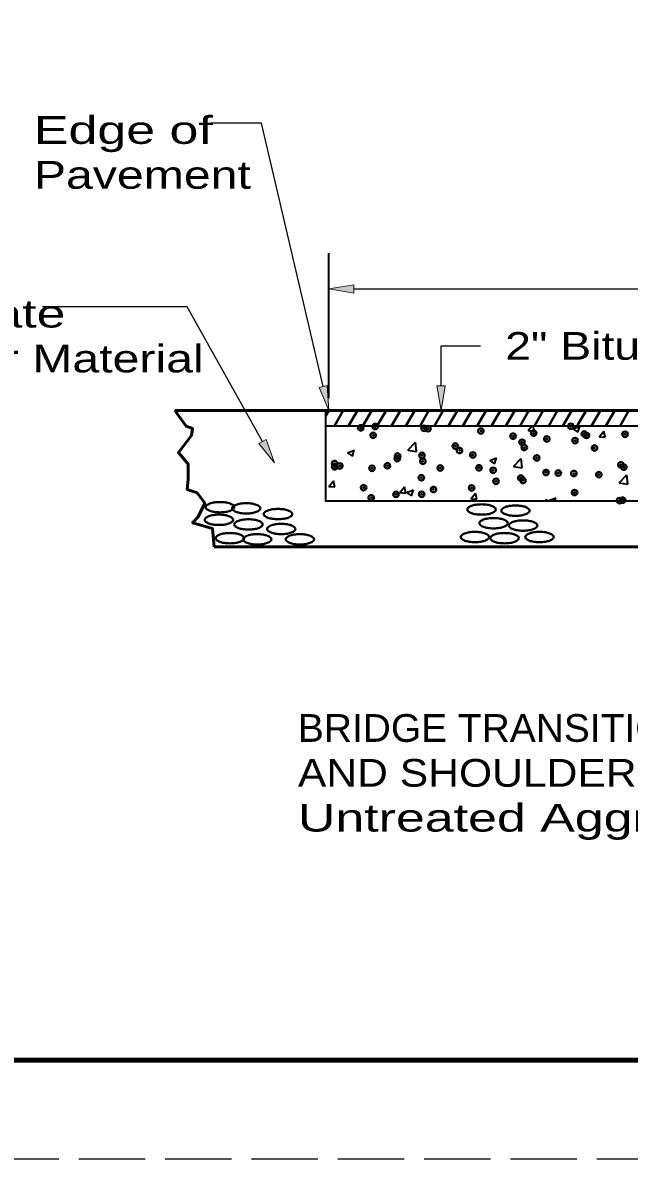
# Model space of a CAD drawing. Extents: x 36.4 to 71.7, y 0.5 to 22.5.
# Drawn here: x 50.93 to 53.99, y 0.48 to 6.22 of the extents above; entities that cross this region are included whole.
import ezdxf

# ---------------------------------------------------------------- set-up
doc = ezdxf.new("R2010")
doc.units = 0
doc.header["$LTSCALE"] = 0.056
doc.header["$PDMODE"] = 32
doc.header["$PDSIZE"] = 0.028
doc.linetypes.add('LONG_DASHED', pattern=[7.5, 6, -1.5])
for name, color, linetype, lineweight in [('1', 7, 'Continuous', 40), ('3', 7, 'Continuous', 13), ('6', 7, 'Continuous', 13)]:
    doc.layers.add(name, color=color, linetype=linetype, lineweight=lineweight)

msp = doc.modelspace()

# ---------------------------------------------------------------- hatches: boundary and pattern name
at = {"layer": '1'}
msp.add_hatch(color=256, dxfattribs=at).paths.add_polyline_path([(52.59792, 4.85283), (52.59792, 4.8945), (52.47292, 4.87358), (52.47292, 4.87358)])
at = {"layer": '3'}
for points in [[(52.46458, 4.38558), (52.42408, 4.376), (52.47292, 4.25908), (52.47292, 4.25908)], [(53.05992, 4.38408), (53.01825, 4.38408), (53.03908, 4.25908), (53.03908, 4.25908)], [(52.15567, 4.11383), (52.11933, 4.09342), (52.19867, 3.99458), (52.19867, 3.99458)]]:
    msp.add_hatch(color=256, dxfattribs=at).paths.add_polyline_path(points)

# ---------------------------------------------------------------- linework, layer by layer
at = {"layer": '1', "lineweight": 35}
for p, q in [((52.47292, 4.3215), (52.47292, 5.05367)), ((53.47892, 4.1585), (53.49825, 4.1815)), ((53.47892, 4.1585), (53.50883, 4.15592)), ((53.50883, 4.15592), (53.50408, 4.1815)), ((53.70483, 4.16767), (53.73983, 4.18108)), ((53.70483, 4.16767), (53.72975, 4.15092)), ((53.72975, 4.15092), (53.73983, 4.18108)), ((53.83758, 4.12717), (53.86167, 4.15592)), ((53.86742, 4.1245), (53.86167, 4.15583)), ((52.87092, 4.05933), (52.90983, 4.09992)), ((52.91542, 4.05242), (52.90992, 4.09992)), ((53.83758, 4.12717), (53.86742, 4.1245)), ((52.56617, 4.04642), (52.60117, 4.05992)), ((52.56617, 4.04642), (52.59108, 4.02967)), ((52.59108, 4.02967), (52.60117, 4.05992)), ((52.87092, 4.05933), (52.91542, 4.0525)), ((53.28475, 4.00642), (53.31975, 4.01983)), ((53.30958, 3.98958), (53.31975, 4.01983)), ((53.28475, 4.00642), (53.30958, 3.98967)), ((53.40458, 3.97658), (53.4435, 4.01717)), ((53.40458, 3.97658), (53.449, 3.96967)), ((53.449, 3.96967), (53.4435, 4.01717)), ((52.47242, 3.87658), (52.4965, 3.90525)), ((52.50233, 3.87392), (52.4965, 3.90525)), ((53.93817, 3.89383), (53.97708, 3.93442)), ((53.98267, 3.88692), (53.97708, 3.93442)), ((52.47242, 3.87658), (52.50233, 3.87392)), ((52.83108, 3.84517), (52.85517, 3.87392)), ((52.86092, 3.84258), (52.85517, 3.87392)), ((52.86467, 3.84517), (52.89967, 3.85858)), ((52.8895, 3.82833), (52.89967, 3.85858)), ((52.8895, 3.82833), (52.89967, 3.85858)), ((53.93817, 3.89383), (53.98267, 3.88692)), ((52.83108, 3.84517), (52.86092, 3.84258)), ((52.86467, 3.84517), (52.8895, 3.82833)), ((53.18967, 3.81383), (53.21375, 3.8425)), ((53.18967, 3.81383), (53.21958, 3.81117)), ((53.21958, 3.81117), (53.21375, 3.8425)), ((53.56575, 3.80325), (53.57242, 3.81117)), ((53.57392, 3.80325), (53.57242, 3.81117)), ((53.58317, 3.80508), (53.61817, 3.8185)), ((53.58317, 3.80508), (53.58592, 3.80325)), ((53.61308, 3.80325), (53.61817, 3.8185))]:
    msp.add_line(p, q, dxfattribs=at)
at = {"layer": '1', "lineweight": 25}
msp.add_line((52.59792, 4.87367), (58.88025, 4.87367), dxfattribs=at)
at = {"layer": '1', "lineweight": 53}
msp.add_line((51.69492, 4.25908), (55.71225, 4.25908), dxfattribs=at)
at = {"layer": '1'}
for p, q in [((52.45633, 4.2305), (52.47292, 4.25908)), ((52.50025, 4.1815), (52.54508, 4.25908)), ((52.57242, 4.1815), (52.61725, 4.25908)), ((52.64458, 4.1815), (52.68942, 4.25908)), ((52.71675, 4.1815), (52.76158, 4.25908)), ((52.78892, 4.1815), (52.83375, 4.25908)), ((52.86108, 4.1815), (52.90592, 4.25908)), ((52.93325, 4.1815), (52.97808, 4.25908)), ((53.00542, 4.1815), (53.05025, 4.25908)), ((53.07758, 4.1815), (53.12242, 4.25908)), ((53.14975, 4.1815), (53.19458, 4.25908)), ((53.22192, 4.1815), (53.26675, 4.25908)), ((53.29417, 4.1815), (53.33892, 4.25908)), ((53.36633, 4.1815), (53.41108, 4.25908)), ((53.4385, 4.1815), (53.48325, 4.25908)), ((53.51067, 4.1815), (53.55542, 4.25908)), ((53.58283, 4.1815), (53.62758, 4.25908)), ((53.655, 4.1815), (53.69975, 4.25908)), ((53.72717, 4.1815), (53.77192, 4.25908)), ((53.79933, 4.1815), (53.84408, 4.25908)), ((53.8715, 4.1815), (53.91625, 4.25908)), ((53.94367, 4.1815), (53.98842, 4.25908))]:
    msp.add_line(p, q, dxfattribs=at)
at = {"layer": '1', "linetype": 'LONG_DASHED', "lineweight": 25}
msp.add_line((71.60142, 0.47742), (36.40142, 0.47742), dxfattribs=at)
at = {"layer": '1', "lineweight": 158}
msp.add_lwpolyline([(71.51808, 21.97742), (71.51808, 0.97742), (39.01808, 0.97742)], dxfattribs=at)
at = {"layer": '1', "lineweight": 13}
msp.add_lwpolyline([(52.59792, 4.85283), (52.59792, 4.8945), (52.47292, 4.87358), (52.47292, 4.87358)], close=True, dxfattribs=at)
at = {"layer": '1', "lineweight": 53}
for points in [[(51.69492, 4.25908), (51.75142, 4.18008), (51.78458, 4.1685), (51.77908, 4.13367), (51.71275, 4.04675), (51.7625, 3.98875), (51.7625, 3.91342), (51.75692, 3.86125), (51.80667, 3.84383), (51.84533, 3.79167), (51.81225, 3.72208), (51.78458, 3.69308), (51.88408, 3.66408), (51.89333, 3.57133)], [(55.71417, 3.809), (55.71417, 3.57133), (51.89333, 3.57133)]]:
    msp.add_lwpolyline(points, dxfattribs=at)
at = {"layer": '1', "lineweight": 35}
for points in [[(52.45633, 4.25908), (52.45633, 4.1815), (55.71225, 4.1815)], [(52.45633, 4.1815), (52.45633, 3.80325), (55.71417, 3.80325)]]:
    msp.add_lwpolyline(points, dxfattribs=at)
at = {"layer": '1'}
for centre, radius, start, end in [((51.8905, 3.73858), 0.05453, 109.95668, 131.23889), ((51.90975, 3.68525), 0.11118, 98.4919, 109.89511), ((51.9225, 3.59967), 0.19777, 89.93573, 98.48922), ((51.92292, 3.60025), 0.19721, 81.49885, 90.05234), ((51.93567, 3.68483), 0.11159, 70.15769, 81.5609), ((51.95492, 3.73883), 0.05433, 48.63999, 69.9222), ((52.04242, 3.67942), 0.11118, 98.4919, 109.89511), ((52.05575, 3.59383), 0.19781, 90.09713, 98.65062), ((52.055, 3.59442), 0.19725, 81.33699, 89.89049), ((52.06833, 3.67942), 0.11118, 70.10489, 81.5081), ((51.86183, 3.77142), 0.01094, 131.65707, 180.41795), ((51.86175, 3.77133), 0.01084, 179.79866, 228.55954), ((51.8905, 3.80417), 0.05453, 228.76111, 250.04332), ((51.90975, 3.8575), 0.11118, 250.10489, 261.5081), ((51.917, 3.53592), 0.19777, 89.93573, 98.48922), ((51.92308, 3.94308), 0.19781, 261.34937, 269.90286), ((51.91742, 3.5365), 0.19721, 81.49885, 90.05234), ((51.92233, 3.9425), 0.19725, 270.10951, 278.663), ((51.93567, 3.85792), 0.11159, 278.43909, 289.84231), ((51.95492, 3.80392), 0.05433, 290.0778, 311.36001), ((51.9945, 3.76558), 0.01098, 180.06351, 228.82439), ((51.99442, 3.7655), 0.01089, 130.95574, 179.71662), ((52.02317, 3.73275), 0.05453, 109.95668, 131.23889), ((52.02317, 3.79833), 0.05453, 228.76111, 250.04332), ((51.98367, 3.77142), 0.01089, 310.95574, 359.71662), ((51.98358, 3.77133), 0.01098, 0.06351, 48.82439), ((52.04242, 3.85167), 0.11118, 250.10489, 261.5081), ((52.05517, 3.93725), 0.19777, 261.51077, 270.06427), ((52.05558, 3.93667), 0.19721, 269.94766, 278.50115), ((52.06833, 3.85167), 0.11118, 278.4919, 289.89511), ((52.08758, 3.73275), 0.05453, 48.76111, 70.04332), ((52.08758, 3.79833), 0.05453, 289.95668, 311.23889), ((52.11633, 3.7655), 0.01089, 0.28337, 49.04425), ((52.11625, 3.76558), 0.01098, 311.1756, 359.93648), ((52.15475, 3.7365), 0.01094, 179.58205, 228.34293), ((52.15467, 3.73658), 0.01084, 131.44045, 180.20133), ((52.18342, 3.70375), 0.05453, 109.95668, 131.23889), ((52.20308, 3.6505), 0.11128, 98.70124, 110.10445), ((52.21542, 3.56492), 0.19777, 89.93573, 98.48922), ((52.21583, 3.5655), 0.19721, 81.49885, 90.05234), ((52.22817, 3.65008), 0.11169, 69.94906, 81.35227), ((52.24783, 3.704), 0.05433, 48.63999, 69.9222), ((52.27658, 3.7365), 0.01089, 0.28337, 49.04425), ((52.2765, 3.73658), 0.01098, 311.1756, 359.93648), ((53.18275, 3.75975), 0.01098, 131.1756, 179.93648), ((53.18267, 3.75983), 0.01089, 180.28337, 229.04425), ((53.21142, 3.727), 0.05453, 109.95668, 131.23889), ((53.21142, 3.79258), 0.05453, 228.76111, 250.04332), ((53.23108, 3.84583), 0.11128, 249.89554, 261.29876), ((53.23067, 3.67367), 0.11118, 98.4919, 109.89511), ((53.24342, 3.58808), 0.19777, 89.93573, 98.48922), ((53.24342, 3.93142), 0.19777, 261.51077, 270.06427), ((53.24383, 3.58867), 0.19721, 81.49885, 90.05234), ((53.24383, 3.93083), 0.19721, 269.94766, 278.50115), ((53.25658, 3.67367), 0.11118, 70.10489, 81.5081), ((53.25617, 3.84583), 0.11128, 278.70124, 290.10445), ((53.27583, 3.727), 0.05453, 48.76111, 70.04332), ((53.27583, 3.79258), 0.05453, 289.95668, 311.23889), ((53.30458, 3.75983), 0.01089, 310.95574, 359.71662), ((53.3045, 3.75975), 0.01098, 0.06351, 48.82439), ((53.35408, 3.754), 0.01098, 180.06351, 228.82439), ((53.354, 3.75392), 0.01089, 130.95574, 179.71662), ((53.38275, 3.72117), 0.05453, 109.95668, 131.23889), ((53.38275, 3.78675), 0.05453, 228.76111, 250.04332), ((53.402, 3.66783), 0.11118, 98.4919, 109.89511), ((53.402, 3.84008), 0.11118, 250.10489, 261.5081), ((53.41533, 3.58283), 0.19725, 90.10951, 98.663), ((53.41458, 3.58225), 0.19781, 81.34937, 89.90286), ((53.42792, 3.66783), 0.11118, 70.10489, 81.5081), ((53.42792, 3.84008), 0.11118, 278.4919, 289.89511), ((53.44717, 3.72117), 0.05453, 48.76111, 70.04332), ((53.44717, 3.78675), 0.05453, 289.95668, 311.23889), ((53.47592, 3.75392), 0.01089, 0.28337, 49.04425), ((53.47583, 3.754), 0.01098, 311.1756, 359.93648), ((51.85625, 3.7075), 0.01089, 130.95574, 179.71662), ((51.85625, 3.70767), 0.01089, 180.28337, 229.04425), ((51.885, 3.67475), 0.05453, 109.95668, 131.23889), ((51.885, 3.74042), 0.05453, 228.76111, 250.04332), ((51.90467, 3.6215), 0.11128, 98.70124, 110.10445), ((51.90467, 3.79367), 0.11128, 249.89554, 261.29876), ((51.917, 3.87925), 0.19777, 261.51077, 270.06427), ((51.91742, 3.87867), 0.19721, 269.94766, 278.50115), ((51.92975, 3.6215), 0.11128, 69.89554, 81.29876), ((51.92975, 3.79367), 0.11128, 278.70124, 290.10445), ((51.94942, 3.67475), 0.05453, 48.76111, 70.04332), ((51.94942, 3.74042), 0.05453, 289.95668, 311.23889), ((51.97817, 3.7075), 0.01089, 0.28337, 49.04425), ((51.97817, 3.70767), 0.01089, 310.95574, 359.71662), ((52.00558, 3.68442), 0.01098, 180.06351, 228.82439), ((52.0055, 3.68433), 0.01089, 130.95574, 179.71662), ((52.03425, 3.65158), 0.05453, 109.95668, 131.23889), ((52.03425, 3.71717), 0.05453, 228.76111, 250.04332), ((52.0535, 3.59825), 0.11118, 98.4919, 109.89511), ((52.06683, 3.51325), 0.19725, 90.10951, 98.663), ((52.06608, 3.51267), 0.19781, 81.34937, 89.90286), ((52.07942, 3.59825), 0.11118, 70.10489, 81.5081), ((52.09867, 3.65158), 0.05453, 48.76111, 70.04332), ((52.09867, 3.71717), 0.05453, 289.95668, 311.23889), ((52.12742, 3.68442), 0.01084, 359.79866, 48.55954), ((52.12733, 3.68433), 0.01094, 311.65707, 0.41795), ((52.18342, 3.76933), 0.05453, 228.76111, 250.04332), ((52.2, 3.62842), 0.05453, 109.95668, 131.23889), ((52.20267, 3.82267), 0.11118, 250.10489, 261.5081), ((52.21925, 3.57508), 0.11118, 98.4919, 109.89511), ((52.21542, 3.90825), 0.19777, 261.51077, 270.06427), ((52.23258, 3.4895), 0.19781, 90.09713, 98.65062), ((52.21583, 3.90767), 0.19721, 269.94766, 278.50115), ((52.23183, 3.49008), 0.19725, 81.33699, 89.89049), ((52.22858, 3.82308), 0.11159, 278.43909, 289.84231), ((52.24517, 3.57467), 0.11159, 70.15769, 81.5609), ((52.24783, 3.76908), 0.05433, 290.0778, 311.36001), ((52.26442, 3.62867), 0.05433, 48.63999, 69.9222), ((53.2435, 3.69025), 0.01094, 131.65707, 180.41795), ((53.24342, 3.69017), 0.01084, 179.79866, 228.55954), ((53.27217, 3.65742), 0.05453, 109.95668, 131.23889), ((53.27217, 3.723), 0.05453, 228.76111, 250.04332), ((53.2915, 3.60367), 0.11159, 98.43909, 109.84231), ((53.30425, 3.51908), 0.19721, 89.94766, 98.50115), ((53.30467, 3.5185), 0.19777, 81.51077, 90.06427), ((53.31742, 3.60408), 0.11118, 70.10489, 81.5081), ((53.33667, 3.65742), 0.05453, 48.76111, 70.04332), ((53.33667, 3.723), 0.05453, 289.95668, 311.23889), ((53.36533, 3.69025), 0.01094, 359.58205, 48.34293), ((53.36542, 3.69017), 0.01084, 311.44045, 0.20133), ((53.39275, 3.67867), 0.01094, 131.65707, 180.41795), ((53.39267, 3.67858), 0.01084, 179.79866, 228.55954), ((53.42142, 3.64583), 0.05453, 109.95668, 131.23889), ((53.41475, 3.92508), 0.19721, 261.49885, 270.05234), ((53.44067, 3.5925), 0.11118, 98.4919, 109.89511), ((53.41517, 3.92567), 0.19777, 269.93573, 278.48922), ((53.45342, 3.50692), 0.19777, 89.93573, 98.48922), ((53.45383, 3.5075), 0.19721, 81.49885, 90.05234), ((53.46658, 3.5925), 0.11118, 70.10489, 81.5081), ((53.48583, 3.64583), 0.05453, 48.76111, 70.04332), ((53.51458, 3.67867), 0.01089, 310.95574, 359.71662), ((53.5145, 3.67858), 0.01098, 0.06351, 48.82439), ((51.9115, 3.61483), 0.01084, 131.44045, 180.20133), ((51.94025, 3.582), 0.05453, 109.95668, 131.23889), ((51.95992, 3.52875), 0.11128, 98.70124, 110.10445), ((51.97225, 3.44317), 0.19777, 89.93573, 98.48922), ((51.97267, 3.44375), 0.19721, 81.49885, 90.05234), ((51.985, 3.52875), 0.11128, 69.89554, 81.29876), ((52.0535, 3.7705), 0.11118, 250.10489, 261.5081), ((52.00467, 3.582), 0.05453, 48.76111, 70.04332), ((52.06625, 3.8555), 0.19721, 261.49885, 270.05234), ((52.04975, 3.60908), 0.01094, 131.65707, 180.41795), ((52.03342, 3.61475), 0.01089, 0.28337, 49.04425), ((52.07842, 3.57625), 0.05453, 109.95668, 131.23889), ((52.09767, 3.52292), 0.11118, 98.4919, 109.89511), ((52.06667, 3.85608), 0.19777, 269.93573, 278.48922), ((52.11042, 3.43733), 0.19777, 89.93573, 98.48922), ((52.07942, 3.7705), 0.11118, 278.4919, 289.89511), ((52.11083, 3.43792), 0.19721, 81.49885, 90.05234), ((52.12358, 3.52292), 0.11118, 70.10489, 81.5081), ((52.17133, 3.66125), 0.01094, 131.65707, 180.41795), ((52.17125, 3.66117), 0.01084, 179.79866, 228.55954), ((52.14283, 3.57625), 0.05453, 48.76111, 70.04332), ((52.2, 3.694), 0.05453, 228.76111, 250.04332), ((52.1715, 3.609), 0.01098, 0.06351, 48.82439), ((52.21925, 3.74733), 0.11118, 250.10489, 261.5081), ((52.23258, 3.83292), 0.19781, 261.34937, 269.90286), ((52.23183, 3.83233), 0.19725, 270.10951, 278.663), ((52.26533, 3.609), 0.01098, 131.1756, 179.93648), ((52.294, 3.57625), 0.05453, 109.95668, 131.23889), ((52.24517, 3.74775), 0.11159, 278.43909, 289.84231), ((52.31325, 3.52292), 0.11118, 98.4919, 109.89511), ((52.26442, 3.69375), 0.05433, 290.0778, 311.36001), ((52.326, 3.43792), 0.19721, 89.94766, 98.50115), ((52.29317, 3.66125), 0.01089, 310.95574, 359.71662), ((52.29308, 3.66117), 0.01098, 0.06351, 48.82439), ((52.32642, 3.43733), 0.19777, 81.51077, 90.06427), ((52.33917, 3.52292), 0.11118, 70.10489, 81.5081), ((52.35842, 3.57625), 0.05453, 48.76111, 70.04332), ((52.38708, 3.60908), 0.01094, 359.58205, 48.34293), ((53.14958, 3.62058), 0.01098, 131.1756, 179.93648), ((53.1495, 3.62067), 0.01089, 180.28337, 229.04425), ((53.17825, 3.58783), 0.05453, 109.95668, 131.23889), ((53.1975, 3.5345), 0.11118, 98.4919, 109.89511), ((53.21083, 3.44892), 0.19781, 90.09713, 98.65062), ((53.21008, 3.4495), 0.19725, 81.33699, 89.89049), ((53.22342, 3.5345), 0.11118, 70.10489, 81.5081), ((53.2915, 3.77675), 0.11159, 250.15769, 261.5609), ((53.24267, 3.58783), 0.05453, 48.76111, 70.04332), ((53.30483, 3.86133), 0.19725, 261.33699, 269.89049), ((53.27142, 3.62067), 0.01089, 310.95574, 359.71662), ((53.27133, 3.62058), 0.01098, 0.06351, 48.82439), ((53.29875, 3.61475), 0.01089, 130.95574, 179.71662), ((53.3275, 3.582), 0.05453, 109.95668, 131.23889), ((53.30408, 3.86192), 0.19781, 270.09713, 278.65062), ((53.34717, 3.52875), 0.11128, 98.70124, 110.10445), ((53.3595, 3.44375), 0.19721, 89.94766, 98.50115), ((53.31742, 3.77633), 0.11118, 278.4919, 289.89511), ((53.35992, 3.44317), 0.19777, 81.51077, 90.06427), ((53.42142, 3.71142), 0.05453, 228.76111, 250.04332), ((53.37225, 3.52875), 0.11128, 69.89554, 81.29876), ((53.44108, 3.76467), 0.11128, 249.89554, 261.29876), ((53.39192, 3.582), 0.05453, 48.76111, 70.04332), ((53.45342, 3.85025), 0.19777, 261.51077, 270.06427), ((53.42067, 3.61483), 0.01084, 359.79866, 48.55954), ((53.45383, 3.84967), 0.19721, 269.94766, 278.50115), ((53.47567, 3.62058), 0.01098, 131.1756, 179.93648), ((53.47558, 3.62067), 0.01089, 180.28337, 229.04425), ((53.50433, 3.58783), 0.05453, 109.95668, 131.23889), ((53.46617, 3.76467), 0.11128, 278.70124, 290.10445), ((53.52358, 3.5345), 0.11118, 98.4919, 109.89511), ((53.48583, 3.71142), 0.05453, 289.95668, 311.23889), ((53.53692, 3.4495), 0.19725, 90.10951, 98.663), ((53.53617, 3.44892), 0.19781, 81.34937, 89.90286), ((53.5495, 3.5345), 0.11118, 70.10489, 81.5081), ((53.56875, 3.58783), 0.05453, 48.76111, 70.04332), ((53.5975, 3.62067), 0.01089, 310.95574, 359.71662), ((53.59742, 3.62058), 0.01098, 0.06351, 48.82439), ((51.91158, 3.61475), 0.01094, 179.58205, 228.34293), ((51.94008, 3.64767), 0.05441, 228.96563, 250.24784), ((51.95992, 3.70092), 0.11128, 249.89554, 261.29876), ((51.97225, 3.7865), 0.19777, 261.51077, 270.06427), ((51.97267, 3.78592), 0.19721, 269.94766, 278.50115), ((51.985, 3.70092), 0.11128, 278.70124, 290.10445), ((52.00483, 3.64767), 0.05441, 289.75216, 311.03436), ((52.04967, 3.609), 0.01084, 179.79866, 228.55954), ((52.03333, 3.61483), 0.01098, 311.1756, 359.93648), ((52.07842, 3.64183), 0.05453, 228.76111, 250.04332), ((52.09767, 3.69517), 0.11118, 250.10489, 261.5081), ((52.111, 3.78075), 0.19781, 261.34937, 269.90286), ((52.11025, 3.78017), 0.19725, 270.10951, 278.663), ((52.12358, 3.69517), 0.11118, 278.4919, 289.89511), ((52.14283, 3.64183), 0.05453, 289.95668, 311.23889), ((52.17158, 3.60908), 0.01089, 310.95574, 359.71662), ((52.26525, 3.60908), 0.01089, 180.28337, 229.04425), ((52.294, 3.64183), 0.05453, 228.76111, 250.04332), ((52.31325, 3.69517), 0.11118, 250.10489, 261.5081), ((52.32658, 3.78017), 0.19725, 261.33699, 269.89049), ((52.32583, 3.78075), 0.19781, 270.09713, 278.65062), ((52.33917, 3.69517), 0.11118, 278.4919, 289.89511), ((52.35842, 3.64183), 0.05453, 289.95668, 311.23889), ((52.38717, 3.609), 0.01084, 311.44045, 0.20133), ((53.17825, 3.65342), 0.05453, 228.76111, 250.04332), ((53.1975, 3.70675), 0.11118, 250.10489, 261.5081), ((53.21083, 3.79233), 0.19781, 261.34937, 269.90286), ((53.21008, 3.79175), 0.19725, 270.10951, 278.663), ((53.22342, 3.70675), 0.11118, 278.4919, 289.89511), ((53.24267, 3.65342), 0.05453, 289.95668, 311.23889), ((53.29883, 3.61483), 0.01098, 180.06351, 228.82439), ((53.32733, 3.64767), 0.05441, 228.96563, 250.24784), ((53.34717, 3.70092), 0.11128, 249.89554, 261.29876), ((53.3595, 3.78592), 0.19721, 261.49885, 270.05234), ((53.35992, 3.7865), 0.19777, 269.93573, 278.48922), ((53.37225, 3.70092), 0.11128, 278.70124, 290.10445), ((53.39208, 3.64767), 0.05441, 289.75216, 311.03436), ((53.42058, 3.61475), 0.01094, 311.65707, 0.41795), ((53.50433, 3.65342), 0.05453, 228.76111, 250.04332), ((53.52358, 3.70675), 0.11118, 250.10489, 261.5081), ((53.53692, 3.79175), 0.19725, 261.33699, 269.89049), ((53.53617, 3.79233), 0.19781, 270.09713, 278.65062), ((53.5495, 3.70675), 0.11118, 278.4919, 289.89511), ((53.56875, 3.65342), 0.05453, 289.95668, 311.23889)]:
    msp.add_arc(centre, radius, start, end, dxfattribs=at)
for p in [(52.70633, 4.17883), (53.69442, 4.18008), (52.63367, 4.17217), (52.69642, 4.13442), (52.95317, 4.16958), (52.97325, 4.16758), (53.24017, 4.15633), (53.40283, 4.13), (53.50708, 4.145), (53.76275, 4.14092), (53.774, 4.13375), (53.96858, 4.13983), (53.11125, 4.07992), (53.44825, 4.0995), (53.45933, 4.07267), (53.57342, 4.116), (53.716, 4.10783), (53.81417, 4.07025), (52.81792, 4.0165), (52.81958, 4.02992), (52.94308, 4.033), (53.1325, 4.05792), (53.19958, 4.03517), (53.52258, 4.02017), (52.50142, 3.99183), (52.50217, 3.97492), (52.528, 3.97983), (52.69033, 3.96792), (52.76833, 3.98058), (52.94708, 4.00317), (53.03525, 3.96933), (53.231, 3.97017), (53.30217, 3.958), (53.947, 3.98525), (53.9625, 3.97342), (52.93942, 3.92008), (53.31675, 3.90225), (53.44192, 3.91875), (53.45325, 3.90617), (53.56908, 3.94675), (53.63125, 3.94367), (53.70992, 3.94142), (53.836, 3.9355), (52.64783, 3.87008), (52.81158, 3.83575), (52.941, 3.83667), (53.00092, 3.86075), (53.19358, 3.86867), (53.71358, 3.84525), (52.68642, 3.81933), (53.94067, 3.8045), (53.95642, 3.807)]:
    msp.add_point(p, dxfattribs=at)
at = {"layer": '3', "lineweight": 25}
for points in [[(52.44433, 4.38083), (52.13233, 5.711), (51.87808, 5.711)], [(52.1375, 4.10367), (51.7565, 4.78325), (51.027, 4.78325)], [(53.03908, 4.38408), (53.03908, 4.58608), (53.23808, 4.58608)]]:
    msp.add_lwpolyline(points, dxfattribs=at)
at = {"layer": '3'}
for points in [[(52.46458, 4.38558), (52.42408, 4.376), (52.47292, 4.25908), (52.47292, 4.25908)], [(53.05992, 4.38408), (53.01825, 4.38408), (53.03908, 4.25908), (53.03908, 4.25908)], [(52.15567, 4.11383), (52.11933, 4.09342), (52.19867, 3.99458), (52.19867, 3.99458)]]:
    msp.add_lwpolyline(points, close=True, dxfattribs=at)
at = {"layer": '6'}
msp.add_line((52.47292, 4.259), (52.473, 4.259), dxfattribs=at)

# ---------------------------------------------------------------- texts
at = {"layer": '3'}
for s, width, p in [('Edge of', 1.4, (50.98275, 5.60658)), ('Pavement', 1.3, (50.98275, 5.37992)), ('Aggregate', 1.4, (49.93267, 4.67883)), ('2" Bituminous Overlay (Skid Resistant Mix)', 1.25, (53.36308, 4.51608)), ('Shoulder Material', 1.3, (49.93267, 4.45217)), ('BRIDGE TRANSITION PAVEMENT', 1.05, (52.31617, 2.586)), ('AND SHOULDER DETAILS (For', 1.15, (52.31617, 2.35933)), ('Untreated Aggregate Shoulders)', 1.4, (52.31617, 2.13267))]:
    msp.add_text(s, height=0.14, dxfattribs=dict(at, width=width)).set_placement(p)

doc.saveas('drawing.dxf')
